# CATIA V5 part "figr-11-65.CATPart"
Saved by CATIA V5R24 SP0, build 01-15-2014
Part number: Part1
Bounding box of the stored display mesh (mm): x -54 to 54, y -91.936 to 93.838, z -12.649 to 110.643
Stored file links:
  D:\KAVITA\CATIA V5-6R2014 Project_ Kavita\CATIA V5-6R2014_partfiles\Partfiles\c11_catia_v5-6r2014_prt\figr-11-65.CATPart
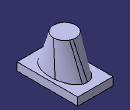
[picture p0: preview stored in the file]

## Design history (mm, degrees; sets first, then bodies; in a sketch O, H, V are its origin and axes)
Set1
  Loft1: Sections (Sketch4; Sketch3)
Body1 (main body)
  Sketch1 on yz-plane, origin (0, 0, 0), H (0, 1, 0), V (0, 0, 1)
    point P1 (93.8379, 11.643)
    line L1 (93.8379, 11.643) -> (93.8379, -12.6487)
    line L2 (93.8379, -12.6487) -> (-91.9362, -12.6487)
    line L3 (-91.9362, -12.6487) -> (-91.9362, 11.643)
    line L4 (-91.9362, 11.643) -> (93.8379, 11.643)
    point P5 (93.8379, 11.643)
    vertical: L1 V, L3 V
    horizontal: L2 H, L4 H
    coincidence: P5 P1
  Pad1: profile Sketch1, direction (1, 0, 0), length 54, mirrored extent
  Sketch2 on face of Pad1, origin (0, 0, 11.643), H (1, 0, 0), V (0, 1, 0)
    circle A1 centre (0, 0) radius 16.7533
    point P1 (16.7533, 0)
    coincidence: A1 P1, P1 H
  Pad2: profile Sketch2, direction (0, 0, 1), length 99
  SewSurface1: SewingRemoveFace face of Pad2, SplitPlane Loft1
  Sketch3 on face of Pad2, origin (0, 0, 110.643), H (1, 0, 0), V (0, 1, 0)
    point P1 (0, 42.8937)
    point P2 (33.9651, 0)
    projected circle E1 centre (0, 0) radius 16.7533 from edge [face of Pad2 | face of Pad2]
    circle A1 centre (0, 0) radius 33.9651
    point P3 (0, 33.9651)
    coincidence: P1 V, P2 H, A1 P2, A1 P3, P3 V
  Sketch4 on face of Pad1, origin (0, 0, 11.643), H (1, 0, 0), V (0, 1, 0)
    ellipse A1 centre (0, 0) semi-axes 69.9141, 43.1918 rotation 90
    point P1 (0, 69.9141)
    point P2 (43.1918, 0)
    coincidence: P1 V, P2 H, A1 P1, A1 P2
